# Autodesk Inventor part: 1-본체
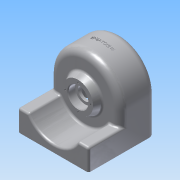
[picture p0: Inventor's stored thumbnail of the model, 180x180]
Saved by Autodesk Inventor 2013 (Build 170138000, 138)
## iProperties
Created: 2015-02
Part Number: 1-본체
Material: 알루미늄 6061
Document SubType Name: Modeling
Designer: Administrator
Density: 2.40731 g/cm^3
Mass: 511.244 g
Surface Area: 706.56 cm^2
Volume: 212.371 cm^3
Author: Administrator
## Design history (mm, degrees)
sketch "스케치1"
  geometry: L1 (-50, 25)-(50, 25); L2 (50, 25)-(50, -25); L3 (50, -25)-(-50, -25); L4 (-50, -25)-(-50, 25); L5 (-50, 25)-(50, -25); L6 (50, 25)-(-50, -25); 1 further point
  constraints: 12 end point, 2 midpoint, 2 parallel, 1 horizontal, 1 perpendicular
  dimensions: "d2" = 50 distance of L3.end L1.start; "d4" = 100 distance of L1.start L1.end
extrude "돌출1" new body sketch "스케치1" distance "d5" = 100; taper "d6" = 0 deg
fillet "모깎기1" dims "d7" = 50
fillet "모깎기2" dims "d8" = 10
feature "쉘1" dims "d9" = 4
sketch "스케치2"
  geometry: C1 r 20 at (40, -50); A1 r 40 centre (40, -50) between (0, -50) and (80, -50) reference; 1 further point
  constraints: 1 centre point, 1 coincident
  dimensions: "d10" = 40 diameter of C1
extrude "돌출2" join sketch "스케치2" distance "d12" = 9; taper "d13" = 0 deg
sketch "스케치3"
  geometry: C1 r 25 at (40, 50); A1 r 40 centre (40, 50) between (80, 50) and (0, 50) reference; 1 further point
  constraints: 1 centre point, 1 coincident
  dimensions: "d14" = 50 diameter of C1
extrude "돌출3" join sketch "스케치3" distance "d16" = 10; taper "d17" = -20 deg
node "작업 평면1"
sketch "스케치4"
  geometry: L1 (90, 0)-(80, 0) reference; L2 (80, 0)-(0, 0) reference; L3 (0, 0)-(-10, 0) reference; L4 (-10, 50)-(-10, 0) reference; L5 (-10, 0)-(90, 0); L6 (90, 30)-(74.641, 30); L7 (-10, 0)-(-10, 30); L8 (5.359, 30)-(-10, 30); L9 (90, 0)-(90, 50) reference; L10 (90, 30)-(90, 0); A1 r 40 centre (40, 50) between (5.359, 30) and (74.641, 30); 2 further points
  constraints: 10 end point, 3 collinear, 2 point on circle, 1 centre point, 1 midpoint, 1 perpendicular, 1 point on line, 1 vertical alignment
  dimensions: "d19" = 80 diameter of A1; "d21" = 50 distance of point (40, 0) A1.centre; "d22" = 30 distance between parallel lines of L6 L1
extrude "돌출4" join sketch "스케치4" stored distance "d23" = 10; taper "d24" = 0 deg
sketch "스케치5"
  geometry: L1 (-40, 0)-(-40, -50) reference; L2 (40, -50)-(-40, -50) reference; L3 (40, -50)-(40, 0) reference; A1 r 40 centre (0, 0) between (40, 0) and (-40, 0) reference; 1 further point
hole "구멍1" diameter "d27" = 20; stored, may be unused: countersink angle "d31" = 90 deg, drill point angle "d33" = 0 deg; dims "d25" = 10, "d26" = 10, "d28" = 6, "d29" = 28, "d30" = 8, "d32" = 10
hole "구멍2" diameter "d36" = 20; stored, may be unused: countersink angle "d40" = 90 deg, drill point angle "d42" = 0 deg; dims "d34" = 10, "d35" = 10, "d37" = 6, "d38" = 28, "d39" = 10, "d41" = 10
sketch "스케치6"
  geometry: C1 r 14 at (0, 0) reference; C2 r 21.36 at (0, 0) reference; A1 r 18 centre (0, 0) between (0, 18) and (0, -18); 3 further points
  constraints: 4 point on circle, 2 horizontal alignment, 2 vertical alignment, 1 centre point, 1 coincident
  dimensions: "d43" = 36 diameter of A1
hole "구멍3" sketch "스케치6" at (0, 18), (0, -18), (18, 0), (-18, 0) diameter "d45" = 2.459; stored, may be unused: countersink angle "d49" = 90 deg, drill point angle "d51" = 118 deg; dims "d46" = 6, "d47" = 28, "d48" = 10, "d50" = 9
sketch "스케치7"
  geometry: L1 (-40, 21)-(40, 21) reference; L2 (50, -70)-(-50, -70) reference; L3 (-41.75, -28)-(41.75, -28); L4 (41.75, -28)-(41.75, -61); L5 (41.75, -61)-(-41.75, -61); L6 (-41.75, -61)-(-41.75, -28); L7 (-41.75, -28)-(41.75, -61); L8 (41.75, -28)-(-41.75, -61); 9 further points
  constraints: 12 end point, 5 coincident, 4 midpoint, 2 parallel, 1 horizontal, 1 perpendicular, 1 vertical alignment
  dimensions: "d52" = 83.5 distance of L4.end L5.end; "d54" = 33 distance of L3.end L4.end; "d56" = 9 distance between parallel lines of L2 L5
hole "구멍4" sketch "스케치7" at (-41.75, -61), (-41.75, -28), (41.75, -28), (41.75, -61) diameter "d57" = 5.134; stored, may be unused: countersink angle "d61" = 90 deg, drill point angle "d63" = 118 deg; dims "d58" = 10, "d59" = 28, "d60" = 10, "d62" = 13
fillet "모깎기3" dims "d64" = 0.3
fillet "모깎기4" dims "d65" = 3
fillet "모깎기5" dims "d66" = 3
node "작업 평면2"
sketch "스케치8"
  geometry: L1 (-40, 37.5)-(40, 37.5) reference; 3 further points
  constraints: 1 midpoint, 1 vertical alignment, 1 other
  dimensions: "d67" = 25 distance from line of point (0, 12.5) L1
feature "엠보싱1" sketch "스케치8" dims "d2" = 50, "d4" = 100, "d68" = 0.5, "d69" = 0
chamfer "모따기1" distance "d70" = 1; stored, may be unused: second distance "d71" = 2, angle "d72" = 45 deg
node "솔리드1"
other parameters: "d18" = -95
